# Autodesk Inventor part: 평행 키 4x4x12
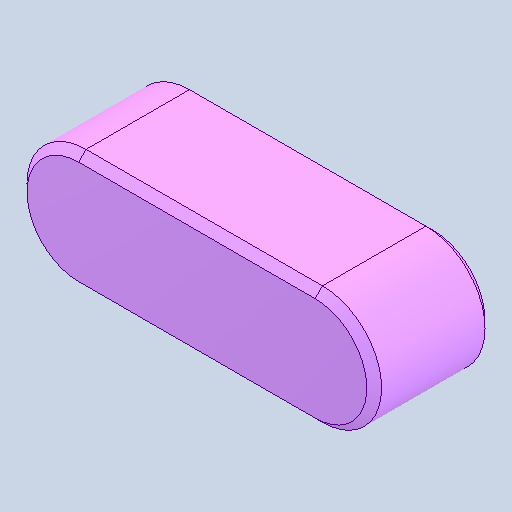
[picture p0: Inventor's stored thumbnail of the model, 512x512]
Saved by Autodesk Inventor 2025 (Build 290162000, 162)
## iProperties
Created: 2026-07
Part Number: 평행 키 4x4x12
Material: 강철, 연강
Description: 키 및 해당 키홈
Document SubType Name: Modeling
Designer: KDI
Density: 7.85 g/cm^3
Appearance: 기본값
Author: jhkim
Sending System: Autodesk Inventor 2027
Preprocessor: ST-DEVELOPER v20.1
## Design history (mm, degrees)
feature "Solid1"
node "솔리드1"
